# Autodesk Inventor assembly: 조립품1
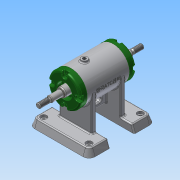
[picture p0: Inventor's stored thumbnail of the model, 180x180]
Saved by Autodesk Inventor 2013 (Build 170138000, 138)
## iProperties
Created: 2016-07
Part Number: 조립품1
Document SubType Name: Assembly
Designer: Administrator
Author: Administrator
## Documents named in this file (5)
- C:\Users\Administrator\Desktop\460708V1028\조립품1.iam
- C:\Users\Administrator\Desktop\460708V1028\본체.ipt
- C:\Users\Administrator\Desktop\460708V1028\축.ipt
- C:\Users\Administrator\Desktop\460708V1028\베어링 15 x 32 x 9.ipt
- C:\Users\Administrator\Desktop\460708V1028\커버.ipt
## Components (2 placed, 1 different names)
1. KS B 2023 6002 - 15 x 32 x 9:1
2. KS B 2023 6002 - 15 x 32 x 9:2
